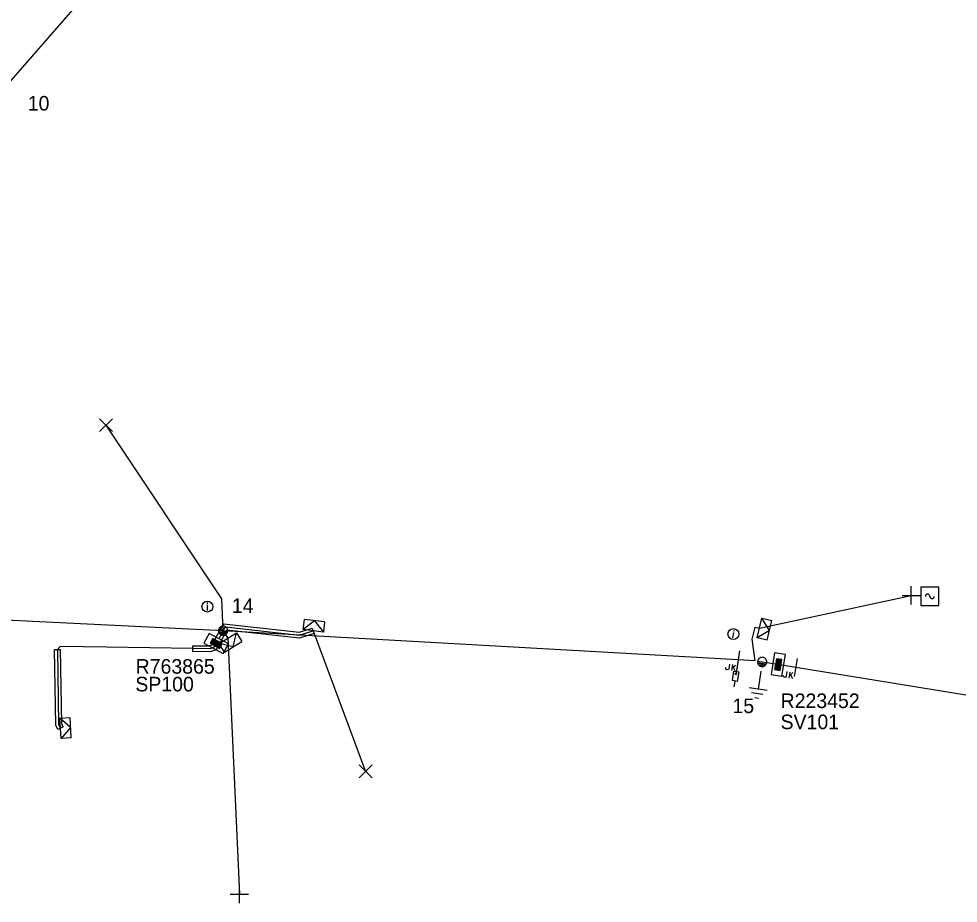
# Model space of a CAD drawing. Extents: x -544780 to -541582, y -1198995 to -1196551.
# Drawn here: x -542049.5 to -541985.1, y -1198924.6 to -1198863.9 of the extents above; entities that cross this region are included whole.
import ezdxf

# ---------------------------------------------------------------- set-up
doc = ezdxf.new("R2010")
doc.units = 0
for name, color, linetype in [('Vrstva 1', 7, 'Continuous'), ('Vrstva 10', 7, 'Continuous'), ('Vrstva 13', 7, 'Continuous'), ('Vrstva 14', 7, 'Continuous'), ('Vrstva 15', 7, 'Continuous'), ('Vrstva 16', 7, 'Continuous'), ('Vrstva 18', 7, 'Continuous'), ('Vrstva 2', 7, 'Continuous'), ('Vrstva 20', 7, 'Continuous'), ('Vrstva 28', 7, 'Continuous'), ('Vrstva 29', 7, 'Continuous'), ('Vrstva 30', 7, 'Continuous'), ('Vrstva 31', 7, 'Continuous'), ('Vrstva 34', 7, 'Continuous'), ('Vrstva 36', 7, 'Continuous'), ('Vrstva 5', 7, 'Continuous'), ('Vrstva 52', 7, 'Continuous'), ('Vrstva 54', 7, 'Continuous'), ('Vrstva 59', 7, 'Continuous'), ('Vrstva 8', 7, 'Continuous'), ('Vrstva 9', 7, 'Continuous')]:
    doc.layers.add(name, color=color, linetype=linetype)

# ---------------------------------------------------------------- blocks, each defined once
blk = doc.blocks.new('NN440')
at = {"layer": 'Vrstva 2'}
for points in [[(0.63, 0), (0.63, 0.06), (0.62, 0.13), (0.6, 0.19), (0.58, 0.25), (0.55, 0.31), (0.51, 0.37), (0.47, 0.42), (0.42, 0.46), (0.37, 0.51), (0.32, 0.54), (0.26, 0.57), (0.2, 0.59), (0.13, 0.61), (0.07, 0.62), (0, 0.63), (-0.06, 0.62), (-0.13, 0.61), (-0.19, 0.59), (-0.26, 0.57), (-0.31, 0.54), (-0.37, 0.51), (-0.42, 0.46), (-0.47, 0.42), (-0.51, 0.37), (-0.54, 0.31), (-0.57, 0.25), (-0.6, 0.19), (-0.62, 0.13), (-0.63, 0.06), (-0.63, 0), (-0.63, -0.07), (-0.62, -0.14), (-0.6, -0.2), (-0.57, -0.26), (-0.54, -0.32), (-0.51, -0.37), (-0.47, -0.43), (-0.42, -0.47), (-0.37, -0.51), (-0.31, -0.55), (-0.26, -0.58), (-0.19, -0.6), (-0.13, -0.62), (-0.06, -0.63), (0, -0.63), (0.07, -0.63), (0.13, -0.62), (0.2, -0.6), (0.26, -0.58), (0.32, -0.55), (0.37, -0.51), (0.42, -0.47), (0.47, -0.43), (0.51, -0.37), (0.55, -0.32), (0.58, -0.26), (0.6, -0.2), (0.62, -0.14), (0.63, -0.07), (0.63, 0)], [(-0.63, 0), (0.63, 0)], [(-0.6, -0.18), (0.57, -0.18)], [(-0.51, -0.32), (0.5, -0.32)], [(-0.37, -0.47), (0.35, -0.47)]]:
    blk.add_lwpolyline(points, dxfattribs=at)
blk = doc.blocks.new('NN840')
at = {"layer": 'Vrstva 15'}
for points in [[(0.003, 0.619), (0.003, -0.631)], [(-0.538, -0.385), (-0.538, -0.71)], [(-0.332, -0.385), (-0.332, -0.798)], [(-0.332, -0.641), (-0.125, -0.385)], [(-0.263, -0.557), (-0.091, -0.798)], [(-0.745, -0.71), (-0.745, -0.66)], [(-0.73, -0.764), (-0.745, -0.71)], [(-0.657, -0.798), (-0.73, -0.764)], [(-0.627, -0.798), (-0.657, -0.798)], [(-0.558, -0.764), (-0.627, -0.798)], [(-0.538, -0.71), (-0.558, -0.764)]]:
    blk.add_lwpolyline(points, dxfattribs=at)
blk = doc.blocks.new('NN770')
at = {"layer": 'Vrstva 10'}
for p, q in [((0.002, 0.187), (0.002, 0.263)), ((0.002, -0.276), (0.002, 0.111))]:
    blk.add_line(p, q, dxfattribs=at)
blk.add_circle((0, -0.008), 0.375, dxfattribs=at)
blk = doc.blocks.new('NN800')
at = {"layer": 'Vrstva 1'}
for points in [[(-0.442, 0.442), (0.442, -0.442)], [(-0.442, -0.442), (0.442, 0.442)]]:
    blk.add_lwpolyline(points, dxfattribs=at)
blk = doc.blocks.new('NN820')
at = {"layer": 'Vrstva 13'}
for points in [[(-0.003, 0.004), (-0.003, -1.049)], [(-0.165, -0.813), (0.165, -0.813)], [(-0.165, -1.473), (-0.165, -0.813)], [(-0.003, -1.049), (-0.062, -0.926)], [(-0.003, -1.049), (0.057, -0.926)], [(0.165, -0.813), (0.165, -1.473)], [(0.165, -1.473), (-0.165, -1.473)], [(-0.003, -1.473), (-0.003, -1.871)]]:
    blk.add_lwpolyline(points, dxfattribs=at)
blk = doc.blocks.new('NN620')
at = {"layer": 'Vrstva 8'}
for points in [[(0.752, 0.004), (-0.748, 0.004)], [(-0.748, 0.004), (-0.748, -0.746)], [(0.752, -0.746), (0.752, 0.004)], [(0.368, -0.18), (-0.376, -0.18)], [(-0.376, -0.18), (-0.376, -0.558)], [(-0.376, -0.558), (0.368, -0.558)], [(0.321, -0.227), (-0.329, -0.227)], [(-0.329, -0.227), (-0.329, -0.51)], [(-0.329, -0.51), (0.321, -0.51)], [(0.274, -0.274), (-0.281, -0.274)], [(-0.281, -0.274), (-0.281, -0.463)], [(-0.281, -0.463), (0.274, -0.463)], [(0.227, -0.321), (-0.234, -0.321)], [(-0.234, -0.321), (-0.234, -0.416)], [(-0.234, -0.416), (0.227, -0.416)], [(-0.193, -0.369), (0.185, -0.369)], [(0.227, -0.416), (0.227, -0.321)], [(0.274, -0.463), (0.274, -0.274)], [(0.321, -0.51), (0.321, -0.227)], [(0.368, -0.558), (0.368, -0.18)], [(-0.748, -0.746), (0.752, -0.746)]]:
    blk.add_lwpolyline(points, dxfattribs=at)
blk = doc.blocks.new('NN630')
at = {"layer": 'Vrstva 9'}
for points in [[(-0.003, -0.7), (-0.703, 0)], [(-0.703, -0.7), (-0.703, 0), (0.697, 0), (0.697, -0.7)], [(-0.003, -0.7), (0.697, 0)], [(-0.703, -0.7), (0.697, -0.7)]]:
    blk.add_lwpolyline(points, dxfattribs=at)
blk = doc.blocks.new('NN810')
at = {"layer": 'Vrstva 14'}
for points in [[(0.004, -0.64), (0.004, -1.89)], [(0.629, -1.89), (-0.621, -1.89)], [(0.388, -2.2), (-0.399, -2.2)], [(0.004, -2.515), (-0.124, -2.515)], [(0.137, -2.515), (0.004, -2.515)]]:
    blk.add_lwpolyline(points, dxfattribs=at)
blk = doc.blocks.new('NN740')
at = {"layer": 'Vrstva 1'}
for points in [[(0.624, 0.624), (-0.626, 0.624)], [(-0.626, 0.624), (-0.626, -0.626)], [(-0.001, -0.001), (-0.002, 0.015), (-0.004, 0.031), (-0.008, 0.046), (-0.014, 0.061), (-0.021, 0.075), (-0.03, 0.089), (-0.04, 0.101), (-0.051, 0.112), (-0.063, 0.123), (-0.077, 0.131), (-0.091, 0.139), (-0.106, 0.145), (-0.121, 0.149), (-0.137, 0.151), (-0.153, 0.152), (-0.169, 0.151), (-0.185, 0.149), (-0.2, 0.145), (-0.215, 0.139), (-0.229, 0.132), (-0.243, 0.123), (-0.255, 0.113), (-0.266, 0.102), (-0.276, 0.09), (-0.285, 0.076), (-0.293, 0.062), (-0.298, 0.047), (-0.303, 0.032), (-0.305, 0.016), (-0.306, 0), (-0.306, -0.001)], [(0.624, -0.626), (0.624, 0.624)], [(-0.626, -0.626), (0.624, -0.626)], [(-0.001, -0.001), (0, -0.017), (0.002, -0.032), (0.006, -0.048), (0.011, -0.062), (0.018, -0.077), (0.026, -0.09), (0.036, -0.102), (0.047, -0.114), (0.059, -0.124), (0.072, -0.133), (0.085, -0.14), (0.1, -0.146), (0.115, -0.15), (0.131, -0.153), (0.146, -0.154), (0.162, -0.154), (0.178, -0.151), (0.193, -0.148), (0.208, -0.142), (0.222, -0.135), (0.235, -0.127), (0.247, -0.118), (0.259, -0.107), (0.269, -0.095), (0.278, -0.082), (0.285, -0.068), (0.291, -0.053), (0.295, -0.038), (0.298, -0.023), (0.299, -0.007), (0.299, -0.006)]]:
    blk.add_lwpolyline(points, dxfattribs=at)

msp = doc.modelspace()

# ---------------------------------------------------------------- linework, layer by layer
at = {"layer": 'Vrstva 1'}
for points in [[(-542080.36, -1198886.573), (-542050.67, -1198868.89), (-542029.05, -1198844.09), (-542003.068, -1198821.935)], [(-542035.5, -1198905.92), (-542063.497, -1198904.556), (-542083.77, -1198903.38)], [(-541998.993, -1198907.983), (-542000.157, -1198907.918), (-542035.5, -1198905.92)], [(-541935.45, -1198918.63), (-541960.059, -1198914.331), (-541998.165, -1198908.116)]]:
    msp.add_lwpolyline(points, dxfattribs=at)
at = {"layer": 'Vrstva 20'}
for points in [[(-542037.567, -1198906.95), (-542036.454, -1198906.969), (-542036.26, -1198906.898), (-542035.676, -1198905.824), (-542035.324, -1198906.016), (-542035.98, -1198907.222), (-542036.386, -1198907.371), (-542037.573, -1198907.35)], [(-542035.67, -1198905.815), (-542035.444, -1198905.447), (-542030.289, -1198906.017), (-542029.378, -1198905.739), (-542029.262, -1198906.121), (-542030.251, -1198906.423), (-542035.236, -1198905.873), (-542035.33, -1198906.025)], [(-542046.67, -1198907.207), (-542046.591, -1198912.31), (-542046.483, -1198912.518), (-542046.837, -1198912.702), (-542046.989, -1198912.41), (-542047.07, -1198907.213)]]:
    msp.add_lwpolyline(points, close=True, dxfattribs=at)
at = {"layer": 'Vrstva 5'}
msp.add_lwpolyline([(-542035.5, -1198905.92), (-542035.799, -1198906.47)], dxfattribs=at)
at = {"layer": 'Vrstva 52'}
for points in [[(-542035.5, -1198905.92), (-542035.34, -1198905.66), (-542030.27, -1198906.22), (-542029.32, -1198905.93)], [(-541998.993, -1198907.983), (-541999.189, -1198906.502), (-541998.982, -1198905.671), (-541998.691, -1198905.735)], [(-542035.875, -1198906.609), (-542036.12, -1198907.06), (-542036.42, -1198907.17), (-542037.57, -1198907.15), (-542043.48, -1198907.05), (-542046.68, -1198907), (-542046.87, -1198907.21), (-542046.79, -1198912.36), (-542046.66, -1198912.61)]]:
    msp.add_lwpolyline(points, dxfattribs=at)
at = {"layer": 'Vrstva 54'}
msp.add_lwpolyline([(-542035.5, -1198905.92), (-542035.166, -1198906.425)], dxfattribs=at)
at = {"layer": 'Vrstva 59'}
for points in [[(-542035.5, -1198905.92), (-542035.582, -1198903.738), (-542043.535, -1198891.822)], [(-541998.691, -1198905.735), (-541988.285, -1198903.501)], [(-542029.32, -1198905.93), (-542025.724, -1198915.57)], [(-542035.166, -1198906.425), (-542034.385, -1198923.989)]]:
    msp.add_lwpolyline(points, dxfattribs=at)

# ---------------------------------------------------------------- block references
at = {"layer": 'Vrstva 13', "xscale": 0.5}
for p, yscale, rotation in [((-542035.5, -1198905.92), 0.5000000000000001, -2.75751633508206), ((-541998.509, -1198908.06), 0.5, -9.263247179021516)]:
    msp.add_blockref('NN440', p, dxfattribs=dict(at, yscale=yscale, rotation=rotation))
at = {"layer": 'Vrstva 15', "rotation": -8.72152772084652}
msp.add_blockref('NN810', (-541998.509, -1198908.06), dxfattribs=at)
at = {"layer": 'Vrstva 16', "rotation": -9.012547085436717}
msp.add_blockref('NN820', (-542000.157, -1198907.918), dxfattribs=at)
at = {"layer": 'Vrstva 18'}
for p, rotation in [((-542000.157, -1198907.918), -9.012547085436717), ((-541996.215, -1198908.434), -9.263247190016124)]:
    msp.add_blockref('NN840', p, dxfattribs=dict(at, rotation=rotation))
at = {"layer": 'Vrstva 28'}
for p, rotation in [((-542035.799, -1198906.47), -28.539985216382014), ((-541997.77, -1198908.18), 80.73699992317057)]:
    msp.add_blockref('NN620', p, dxfattribs=dict(at, rotation=rotation))
at = {"layer": 'Vrstva 31'}
for p, rotation in [((-542029.32, -1198905.93), 172.87498355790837), ((-541998.691, -1198905.735), 76.98648892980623), ((-542035.166, -1198906.425), 31.333055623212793), ((-542046.66, -1198912.61), 93.57634642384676)]:
    msp.add_blockref('NN630', p, dxfattribs=dict(at, rotation=rotation))
at = {"layer": 'Vrstva 34'}
for name, p in [('NN800', (-542043.535, -1198891.822)), ('NN740', (-541987.003, -1198903.562)), ('NN800', (-542025.724, -1198915.57))]:
    msp.add_blockref(name, p, dxfattribs=at)
at = {"layer": 'Vrstva 34', "rotation": 45}
for p in [(-541988.285, -1198903.501), (-542034.385, -1198923.989)]:
    msp.add_blockref('NN800', p, dxfattribs=at)
at = {"layer": 'Vrstva 36'}
for p, rotation in [((-542036.576, -1198904.257), -0.004848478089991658), ((-542000.48, -1198906.143), -8.72152772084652)]:
    msp.add_blockref('NN770', p, dxfattribs=dict(at, rotation=rotation))

# ---------------------------------------------------------------- texts
at = {"layer": 'Vrstva 14'}
for s, p in [('10', (-542048.906, -1198870.237)), ('14', (-542034.897, -1198904.702)), ('15', (-542000.548, -1198911.572))]:
    msp.add_text(s, height=1, dxfattribs=at).set_placement(p)
at = {"layer": 'Vrstva 29'}
for s, p in [('R763865', (-542041.504, -1198908.868)), ('R223452', (-541997.247, -1198911.227))]:
    msp.add_text(s, height=1, dxfattribs=at).set_placement(p)
at = {"layer": 'Vrstva 30'}
for s, p in [('SP100', (-542041.524, -1198910.084)), ('SV101', (-541997.247, -1198912.675))]:
    msp.add_text(s, height=1, dxfattribs=at).set_placement(p)

doc.saveas('drawing.dxf')
